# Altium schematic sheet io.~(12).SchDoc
size Letter
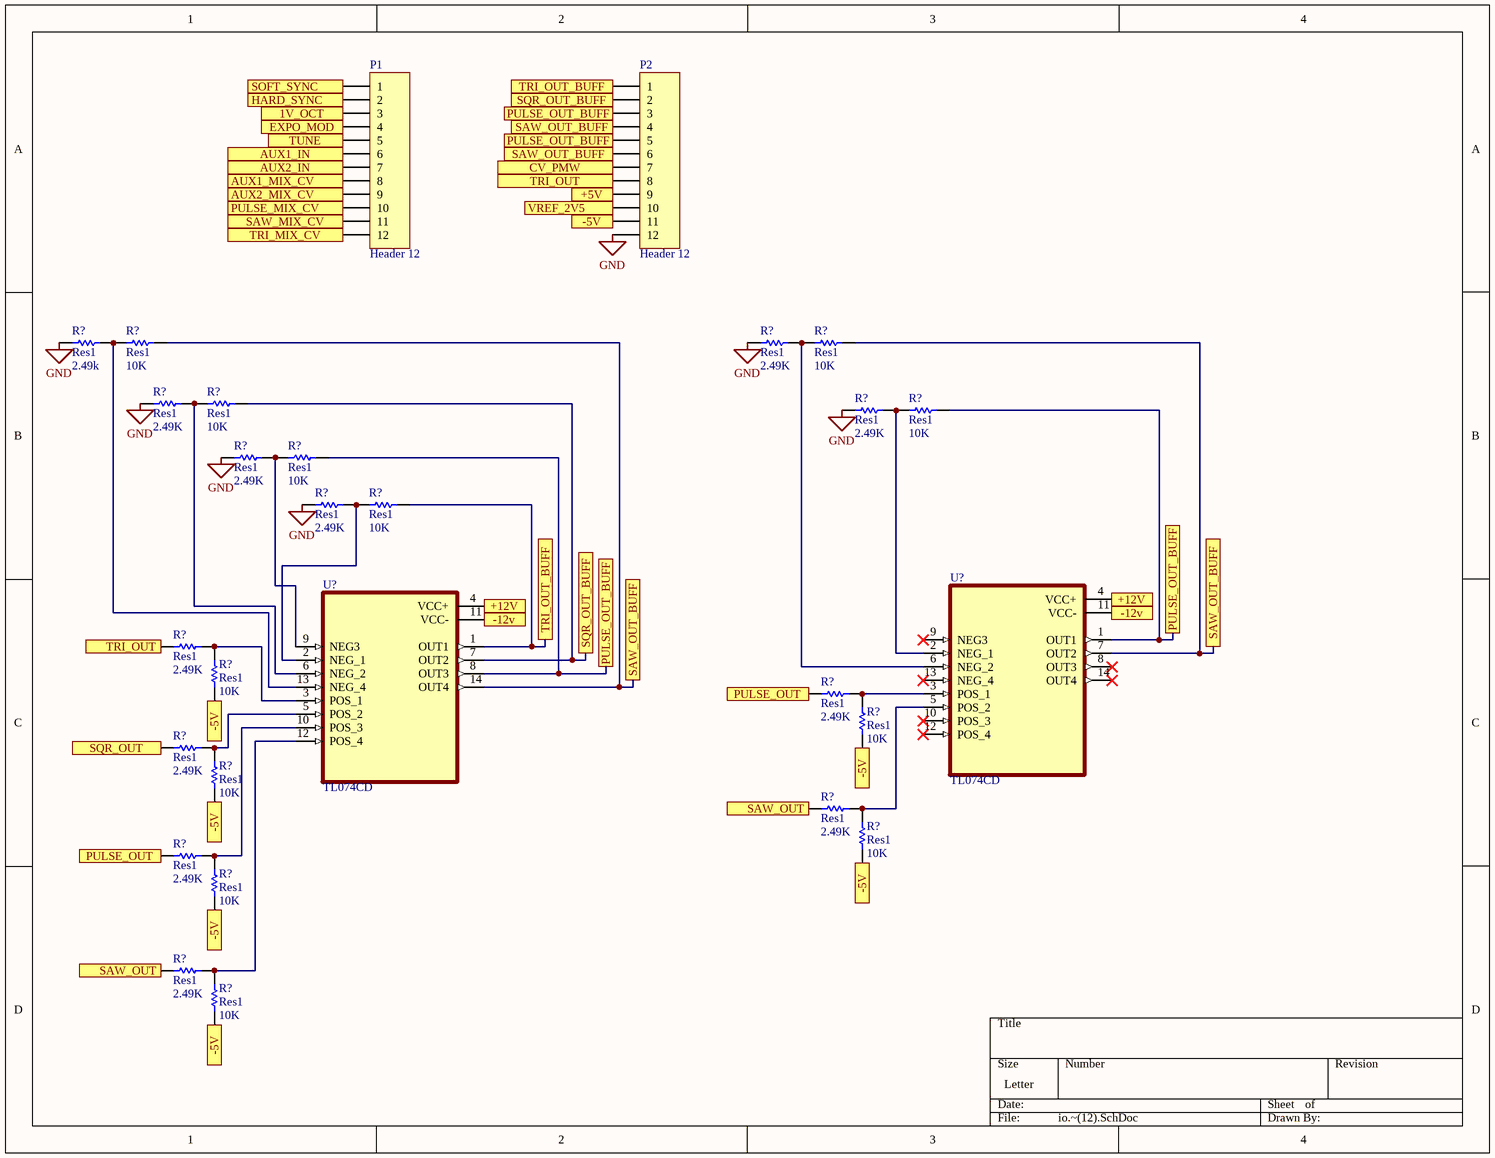
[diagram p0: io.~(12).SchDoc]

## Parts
(Parts that share a designator on the sheet are numbered #1, #2 ... from top to bottom, then left to right.)
P1  Header 12  [HDR1X12]
P2  Header 12  [HDR1X12]
R?#1  Res1  value 2.49k  [AXIAL-0.3]
R?#2  Res1  value 10K  [AXIAL-0.3]
R?#3  Res1  value 2.49K  [AXIAL-0.3]
R?#4  Res1  value 10K  [AXIAL-0.3]
R?#5  Res1  value 2.49K  [AXIAL-0.3]
R?#6  Res1  value 10K  [AXIAL-0.3]
R?#7  Res1  value 2.49K  [AXIAL-0.3]
R?#8  Res1  value 10K  [AXIAL-0.3]
R?#9  Res1  value 2.49K  [AXIAL-0.3]
R?#10  Res1  value 10K  [AXIAL-0.3]
R?#11  Res1  value 2.49K  [AXIAL-0.3]
R?#12  Res1  value 10K  [AXIAL-0.3]
R?#13  Res1  value 2.49K  [AXIAL-0.3]
R?#14  Res1  value 2.49K  [AXIAL-0.3]
R?#15  Res1  value 10K  [AXIAL-0.3]
R?#16  Res1  value 2.49K  [AXIAL-0.3]
R?#17  Res1  value 10K  [AXIAL-0.3]
R?#18  Res1  value 10K  [AXIAL-0.3]
R?#19  Res1  value 2.49K  [AXIAL-0.3]
R?#20  Res1  value 2.49K  [AXIAL-0.3]
R?#21  Res1  value 10K  [AXIAL-0.3]
R?#22  Res1  value 10K  [AXIAL-0.3]
R?#23  Res1  value 2.49K  [AXIAL-0.3]
R?#24  Res1  value 10K  [AXIAL-0.3]
U?#1  TL074CD  [SOIC127P600X175-14N]
U?#2  TL074CD  [SOIC127P600X175-14N]

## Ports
1V_OCT, +5V, +12V, -5V, -12v, AUX1_IN, AUX1_MIX_CV, AUX2_IN, AUX2_MIX_CV, CV_PMW, EXPO_MOD, HARD_SYNC, PULSE_MIX_CV, PULSE_OUT, PULSE_OUT_BUFF, SAW_MIX_CV, SAW_OUT, SAW_OUT_BUFF, SOFT_SYNC, SQR_OUT, SQR_OUT_BUFF, TRI_MIX_CV, TRI_OUT, TRI_OUT_BUFF, TUNE, VREF_2V5

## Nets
GND: P2.12 R?#1.1 R?#3.1 R?#5.1 R?#7.1 R?#9.1 R?#11.1
1V_OCT: P1.3 ; port 1V_OCT
+5V: P2.9 ; port +5V
+12V: U?#1.4(VCC+) U?#2.4(VCC+) ; port +12V
-5V: P2.11 R?#15.1 R?#17.1 R?#18.1 R?#21.1 R?#22.1 R?#24.1 ; port -5V
-12v: U?#1.11(VCC-) U?#2.11(VCC-) ; port -12v
AUX1_IN: P1.6 ; port AUX1_IN
AUX1_MIX_CV: P1.8 ; port AUX1_MIX_CV
AUX2_IN: P1.7 ; port AUX2_IN
AUX2_MIX_CV: P1.9 ; port AUX2_MIX_CV
CV_PMW: P2.7 ; port CV_PMW
EXPO_MOD: P1.4 ; port EXPO_MOD
HARD_SYNC: P1.2 ; port HARD_SYNC
PULSE_MIX_CV: P1.10 ; port PULSE_MIX_CV
PULSE_OUT: R?#14.1 R?#20.1 ; port PULSE_OUT
PULSE_OUT_BUFF: P2.3 P2.5 R?#8.2 R?#10.2 U?#1.1(OUT1) U?#2.8(OUT3) ; port PULSE_OUT_BUFF
SAW_MIX_CV: P1.11 ; port SAW_MIX_CV
SAW_OUT: R?#19.1 R?#23.1 ; port SAW_OUT
SAW_OUT_BUFF: P2.4 P2.6 R?#2.2 R?#4.2 U?#1.7(OUT2) U?#2.14(OUT4) ; port SAW_OUT_BUFF
SOFT_SYNC: P1.1 ; port SOFT_SYNC
SQR_OUT: R?#16.1 ; port SQR_OUT
SQR_OUT_BUFF: P2.2 R?#6.2 U?#2.7(OUT2) ; port SQR_OUT_BUFF
TRI_MIX_CV: P1.12 ; port TRI_MIX_CV
TRI_OUT: P2.8 R?#13.1 ; port TRI_OUT
TRI_OUT_BUFF: P2.1 R?#12.2 U?#2.1(OUT1) ; port TRI_OUT_BUFF
TUNE: P1.5 ; port TUNE
VREF_2V5: P2.10 ; port VREF_2V5
NetR?#1_2: R?#1.2 R?#2.1 U?#2.13(NEG_4)
NetR?#3_2: R?#3.2 R?#4.1 U?#1.6(NEG_2)
NetR?#5_2: R?#5.2 R?#6.1 U?#2.6(NEG_2)
NetR?#7_2: R?#7.2 R?#8.1 U?#1.2(NEG_1)
NetR?#9_2: R?#9.2 R?#10.1 U?#2.9(NEG3)
NetR?#11_2: R?#11.2 R?#12.1 U?#2.2(NEG_1)
NetR?#13_2: R?#13.2 R?#15.2 U?#2.3(POS_1)
NetR?#14_2: R?#14.2 R?#17.2 U?#1.3(POS_1)
NetR?#16_2: R?#16.2 R?#18.2 U?#2.5(POS_2)
NetR?#19_2: R?#19.2 R?#21.2 U?#1.5(POS_2)
NetR?#20_2: R?#20.2 R?#22.2 U?#2.10(POS_3)
NetR?#23_2: R?#23.2 R?#24.2 U?#2.12(POS_4)

Not connected (* = marked no-connect by the designer): U?#1 8(OUT3)* 9(NEG3)* 10(POS_3)* 12(POS_4)* 13(NEG_4)* 14(OUT4)*

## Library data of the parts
P1 P2 = Header 12: Header, 12-Pin
R?#1-R?#24 = Res1: Resistor
U?#1 U?#2 = TL074CD: Quad Low-Noise JFET-Input General-Purpose Operational Amplifier 14-SOIC 0 to 70; MF: Texas Instruments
